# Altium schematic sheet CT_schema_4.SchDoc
size 321 x 189 mm
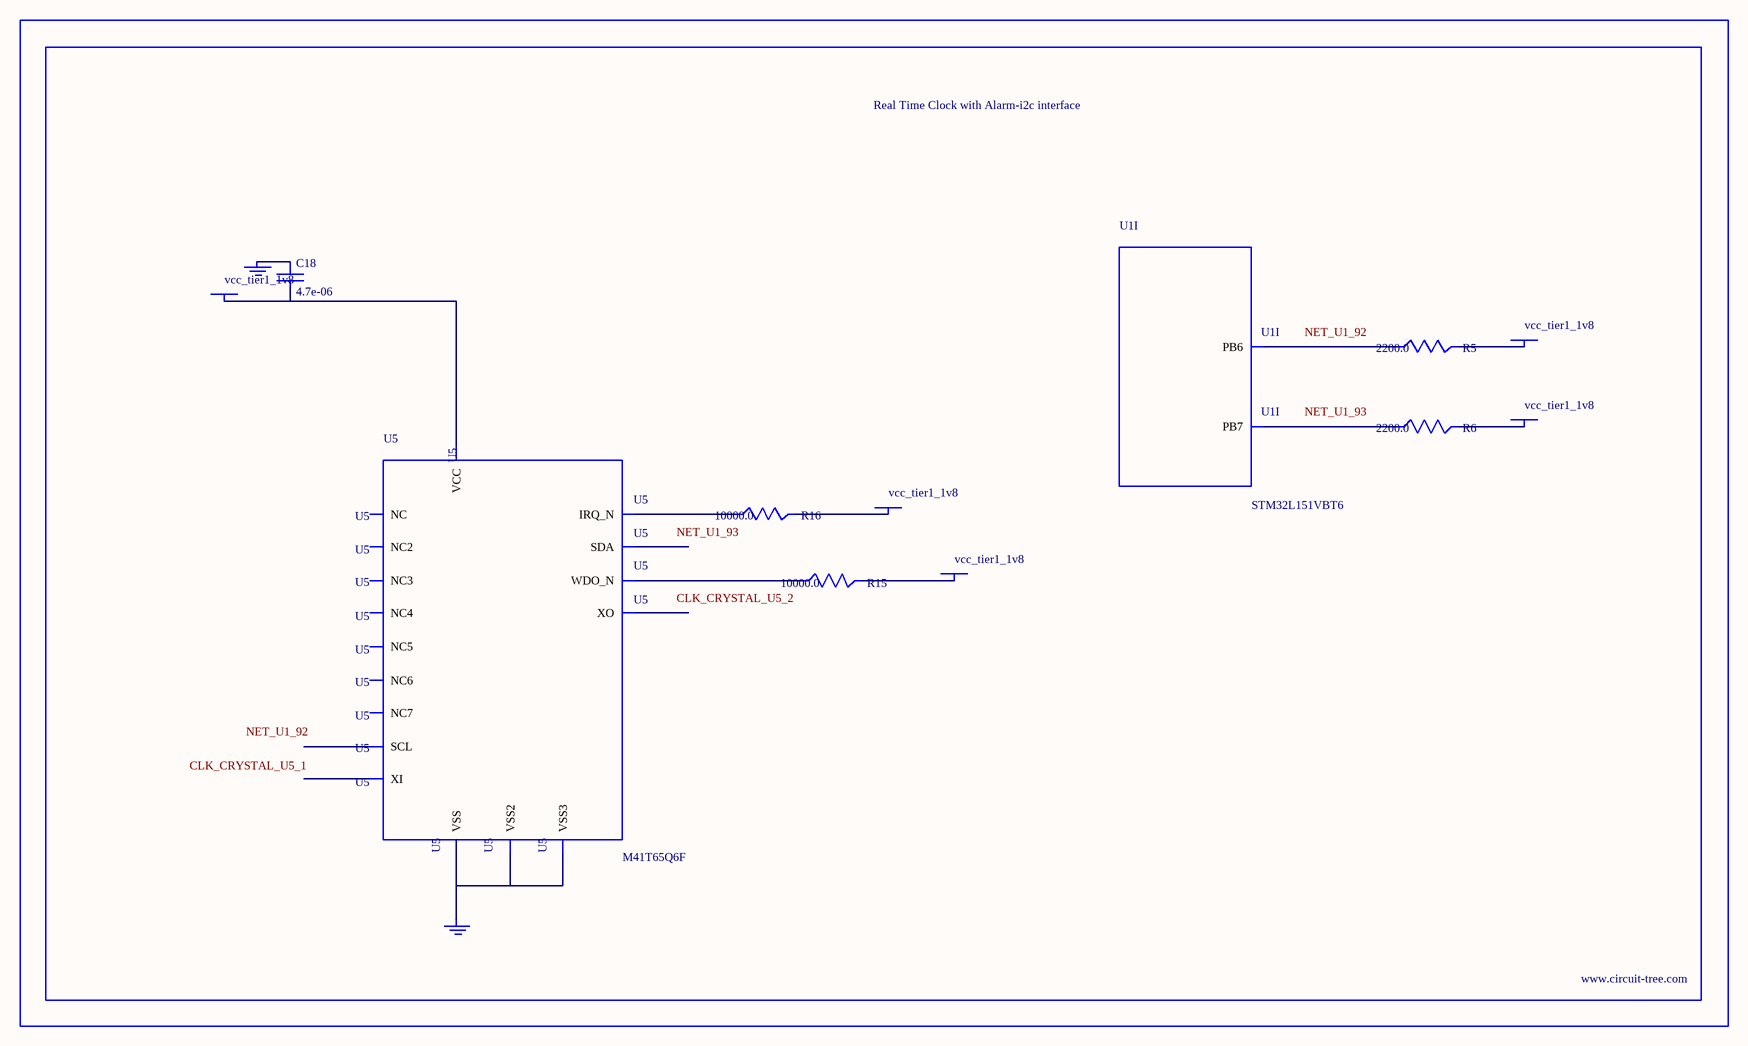
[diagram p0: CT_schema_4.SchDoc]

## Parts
BORDER3  (no value)
C18  4.7e-06  [C0805]
GND_INSTANCE_3_0  (no value)
GND_INSTANCE_3_1  (no value)
POWER_INSTANCE_3_0  vcc_tier1_1v8
POWER_INSTANCE_3_1  vcc_tier1_1v8
POWER_INSTANCE_3_2  vcc_tier1_1v8
POWER_INSTANCE_3_3  vcc_tier1_1v8
POWER_INSTANCE_3_4  vcc_tier1_1v8
R5  2200.0  [R0603]
R6  2200.0  [R0603]
R15  10000.0  [R0603]
R16  10000.0  [R0603]
U1  STM32L151VBT6  [LQFP100]  (part I of 11)
U5  M41T65Q6F  [M41T65_QFN-16]

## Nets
NetC18_1: C18.1 GND_INSTANCE_3_0.0(GND)
NetC18_2: C18.2 POWER_INSTANCE_3_2.0(PWR) U5.14(VCC)
NetGND_INSTANCE_3_1_0: GND_INSTANCE_3_1.0(GND) U5.3(VSS) U5.5(VSS2) U5.17(VSS3)
NetPOWER_INSTANCE_3_0_0: POWER_INSTANCE_3_0.0(PWR) R15.2
NetPOWER_INSTANCE_3_1_0: POWER_INSTANCE_3_1.0(PWR) R16.2
NetPOWER_INSTANCE_3_3_0: POWER_INSTANCE_3_3.0(PWR) R5.2
NetPOWER_INSTANCE_3_4_0: POWER_INSTANCE_3_4.0(PWR) R6.2
NetR5_1: R5.1 U1.92(PB6)
NetR6_1: R6.1 U1.93(PB7)
NetR15_1: R15.1 U5.4(WDO_N)
NetR16_1: R16.1 U5.11(IRQ_N)

Not connected (* = marked no-connect by the designer): U5 1(XI) 2(XO) 6(NC) 7(NC2) 8(NC3) 9(SDA) 10(SCL) 12(NC4) 13(NC5) 15(NC6) 16(NC7)

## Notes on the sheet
- Labels drawn without touching a wire or pin: CLK_CRYSTAL_U5_1, CLK_CRYSTAL_U5_2, NET_U1_92, NET_U1_93

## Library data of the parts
BORDER3 = BORDER_PAGE3
C18 = C0805C475K4RACTU
GND_INSTANCE_3_0 GND_INSTANCE_3_1 = GND
POWER_INSTANCE_3_0-POWER_INSTANCE_3_4 = PWR
R5 R6 = RC0603JR-072K2L
R15 R16 = RC0603JR-0710KL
